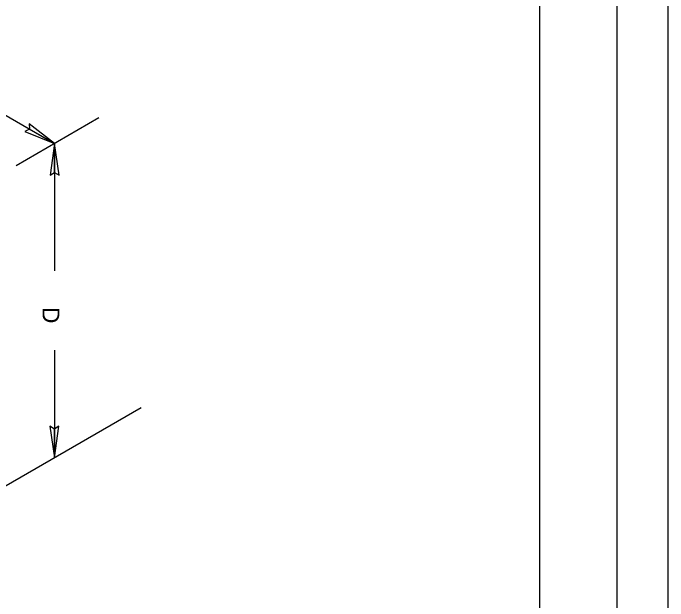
# Model space of a CAD drawing. Extents: x -120.7 to -50.3, y -20.2 to 3.8.
# Drawn here: x -54.911 to -50.259, y -4.59 to -0.416 of the extents above; entities that cross this region are included whole.
import ezdxf

# ---------------------------------------------------------------- set-up
doc = ezdxf.new("R2010")
doc.units = 0
for name, color, linetype in [('Default', 7, 'Continuous'), ('PR_Dimensions', 7, 'Continuous'), ('SHT_Plot_Shape_Full', 7, 'Continuous'), ('SHT_Plot_Shape_Half', 7, 'Continuous'), ('SHT_Sheet_Border', 7, 'Continuous'), ('TYP_Typical_Section_Txt', 7, 'Continuous')]:
    doc.layers.add(name, color=color, linetype=linetype)

# ---------------------------------------------------------------- blocks, each defined once
blk = doc.blocks.new('AR32_1')
at = {"layer": 'Default'}
for p, q in [((0, 0), (-11.43, 1.6)), ((-11.43, 1.6), (-10.39, -0.01)), ((-11.42, -1.63), (0, 0)), ((-10.39, -0.01), (-11.42, -1.63))]:
    blk.add_line(p, q, dxfattribs=at)

msp = doc.modelspace()

# ---------------------------------------------------------------- linework, layer by layer
at = {"layer": 'PR_Dimensions'}
for p, q in [((-55.6619, -0.7393), (-54.6173, -1.3424)), ((-54.3016, -1.1601), (-54.8898, -1.4998)), ((-54.7965, -1.2027), (-54.7946, -1.2401)), ((-54.6173, -1.3424), (-54.7965, -1.2027)), ((-54.7946, -1.2404), (-54.8281, -1.2578)), ((-54.6173, -1.3424), (-54.7945, -1.2402)), ((-54.8281, -1.2578), (-54.6173, -1.3424)), ((-54.6173, -1.3424), (-54.6487, -1.5674)), ((-54.6173, -1.3424), (-54.6173, -2.2455)), ((-54.6173, -1.547), (-54.6173, -1.3424)), ((-54.5853, -1.5673), (-54.6173, -1.3424)), ((-54.6173, -1.3424), (-54.617, -1.547)), ((-54.6487, -1.5674), (-54.6173, -1.5472)), ((-54.6173, -1.5472), (-54.6173, -1.547)), ((-54.617, -1.547), (-54.5853, -1.5673)), ((-54.6173, -2.8104), (-54.6173, -3.5742)), ((-54.0005, -3.2181), (-55.1594, -3.8871)), ((-54.6176, -3.3696), (-54.6494, -3.3493)), ((-54.6494, -3.3493), (-54.6173, -3.5742)), ((-54.6173, -3.5742), (-54.5859, -3.3492)), ((-54.5859, -3.3492), (-54.6173, -3.3694)), ((-54.6173, -3.5742), (-54.6173, -3.3696))]:
    msp.add_line(p, q, dxfattribs=at)
for points in [[(-54.7946, -1.2401), (-54.7945, -1.2402), (-54.6173, -1.3424)], [(-54.7945, -1.2402), (-54.7946, -1.2404)], [(-54.6173, -3.3696), (-54.6176, -3.3696)], [(-54.6173, -3.3694), (-54.6173, -3.3696), (-54.6173, -3.5742)]]:
    msp.add_lwpolyline(points, dxfattribs=at)
at = {"layer": 'SHT_Plot_Shape_Full'}
msp.add_lwpolyline([(-86.2592, 3.7586), (-50.2592, 3.7586), (-50.2592, -20.2414), (-86.2592, -20.2414)], close=True, dxfattribs=at)
at = {"layer": 'SHT_Plot_Shape_Half'}
msp.add_lwpolyline([(-84.6217, 2.9337), (-50.6217, 2.9337), (-50.6217, -19.0663), (-84.6217, -19.0663)], close=True, dxfattribs=at)
at = {"layer": 'SHT_Sheet_Border'}
msp.add_lwpolyline([(-51.1717, -18.5663), (-82.6717, -18.5663), (-82.6717, 2.4337), (-51.1717, 2.4337)], close=True, dxfattribs=at)

# ---------------------------------------------------------------- block references
at = {"layer": 'PR_Dimensions'}
for p, xscale, yscale, rotation in [((-54.6173, -1.3424), 0.01968511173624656, 0.01968511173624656, -29.999935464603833), ((-54.6173, -1.3424), 0.019685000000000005, 0.019685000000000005, 90.00000000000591), ((-54.6173, -3.5742), 0.019685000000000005, 0.019685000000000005, -90.00000000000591)]:
    msp.add_blockref('AR32_1', p, dxfattribs=dict(at, xscale=xscale, yscale=yscale, rotation=rotation))

# ---------------------------------------------------------------- texts
at = {"layer": 'TYP_Typical_Section_Txt'}
msp.add_text('D', height=0.12, rotation=270, dxfattribs=at).set_placement((-54.7022, -2.5035))

doc.saveas('drawing.dxf')
